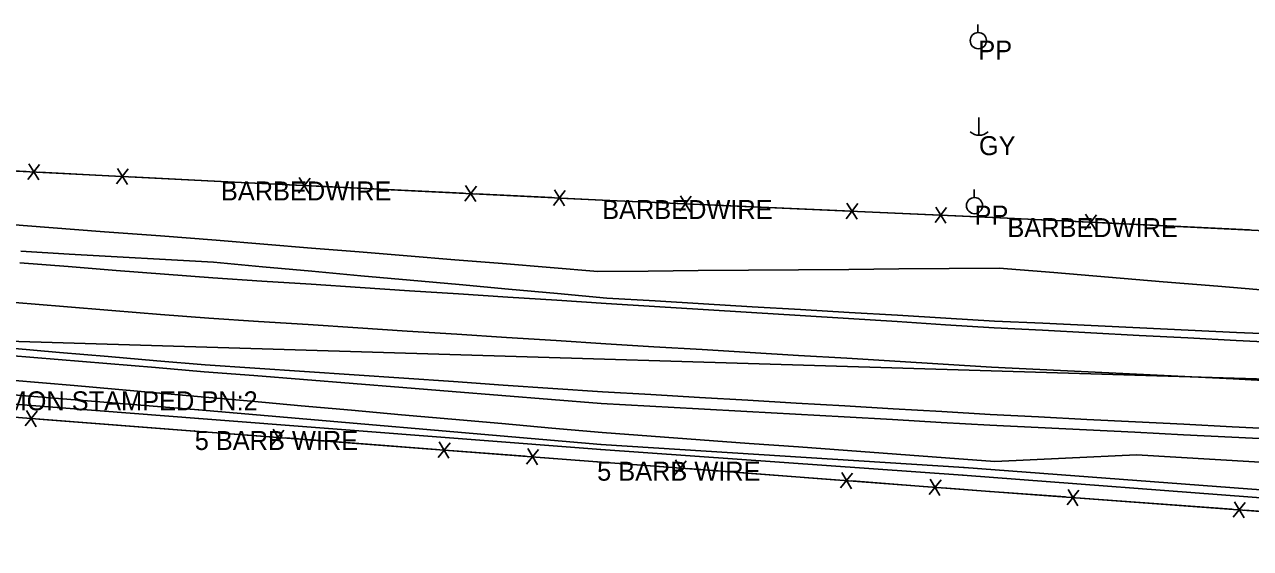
# Model space of a CAD drawing. Extents: x 675481 to 678499, y 212715 to 215285.
# Drawn here: x 675952.1 to 676275.5, y 214677.2 to 214815.3 of the extents above; entities that cross this region are included whole.
import ezdxf

# ---------------------------------------------------------------- set-up
doc = ezdxf.new("R2010")
doc.units = 0
for name, color, linetype in [('S_BASELINE', 7, 'Continuous'), ('S_DITCHLINE', 7, 'Continuous'), ('S_EDGE_PAVEMENT', 7, 'Continuous'), ('S_FENCE', 7, 'Continuous'), ('S_FENCE_ANNOT', 7, 'Continuous'), ('S_FIBER_OPTIC_CABLE', 7, 'Continuous'), ('S_MSC_PT_SYM', 7, 'Continuous'), ('S_PAVEMENT_CROWN', 7, 'Continuous'), ('S_PRIMARY_CTL_ANNOT', 7, 'Continuous'), ('S_SHOULDER', 7, 'Continuous'), ('S_UTILITY_POLE', 7, 'Continuous'), ('S_UTILITY_POLE_ANNOT', 7, 'Continuous'), ('S_UTL_PT_SYM', 7, 'Continuous')]:
    doc.layers.add(name, color=color, linetype=linetype)

msp = doc.modelspace()

# ---------------------------------------------------------------- linework, layer by layer
at = {"layer": 'S_BASELINE'}
msp.add_line((675887.93, 214733.6), (676879.32, 214703.75), dxfattribs=at)
at = {"layer": 'S_DITCHLINE'}
for points in [[(675943.76, 214762.96), (675958.47, 214761.83), (675973.19, 214760.71), (675987.9, 214759.58), (676002.61, 214758.45), (676015.2, 214757.42), (676027.79, 214756.39), (676040.37, 214755.36), (676052.96, 214754.33), (676065.55, 214753.31), (676078.13, 214752.28), (676090.72, 214751.25), (676103.31, 214750.22), (676116.54, 214750.33), (676129.78, 214750.44), (676143.02, 214750.56), (676156.25, 214750.67), (676169.49, 214750.78), (676182.72, 214750.89), (676195.96, 214751.01), (676209.2, 214751.12), (676223.61, 214749.92), (676238.03, 214748.72), (676252.45, 214747.52), (676266.87, 214746.32), (676281.29, 214745.11)], [(675948.44, 214721.58), (675965.17, 214720.1), (675981.9, 214718.63), (675998.63, 214717.15), (676011.85, 214715.97), (676025.07, 214714.8), (676038.3, 214713.62), (676051.52, 214712.44), (676064.74, 214711.27), (676077.97, 214710.09), (676091.19, 214708.91), (676104.41, 214707.74), (676117.36, 214706.79), (676130.31, 214705.84), (676143.25, 214704.88), (676156.2, 214703.93), (676169.15, 214702.98), (676182.1, 214702.03), (676195.04, 214701.08), (676207.99, 214700.13), (676226.7, 214700.98), (676245.41, 214701.83), (676266.15, 214700.62), (676286.9, 214699.42)]]:
    msp.add_lwpolyline(points, dxfattribs=at)
at = {"layer": 'S_EDGE_PAVEMENT'}
for points in [[(675950.84, 214752.51), (675963.55, 214751.51), (675976.27, 214750.51), (675988.98, 214749.52), (676001.7, 214748.52), (676014.67, 214747.68), (676027.64, 214746.83), (676040.61, 214745.99), (676053.59, 214745.15), (676066.56, 214744.31), (676079.53, 214743.46), (676092.51, 214742.62), (676105.48, 214741.78), (676118.27, 214740.98), (676131.06, 214740.18), (676143.85, 214739.38), (676156.65, 214738.58), (676169.44, 214737.78), (676182.23, 214736.98), (676195.02, 214736.18), (676207.81, 214735.38), (676220.58, 214734.71), (676233.36, 214734.04), (676246.13, 214733.37), (676258.9, 214732.7), (676271.67, 214732.03), (676284.45, 214731.36)], [(675948.5, 214729.96), (675961.32, 214728.87), (675974.13, 214727.78), (675986.94, 214726.69), (675999.75, 214725.59), (676012.85, 214724.71), (676025.94, 214723.82), (676039.04, 214722.93), (676052.13, 214722.05), (676065.22, 214721.16), (676078.32, 214720.27), (676091.41, 214719.38), (676104.5, 214718.5), (676117.29, 214717.75), (676130.08, 214717), (676142.86, 214716.26), (676155.65, 214715.51), (676168.44, 214714.76), (676181.22, 214714.02), (676194.01, 214713.27), (676206.8, 214712.52), (676219.56, 214711.87), (676232.33, 214711.22), (676245.1, 214710.56), (676257.86, 214709.91), (676270.63, 214709.26), (676283.4, 214708.6)]]:
    msp.add_lwpolyline(points, dxfattribs=at)
at = {"layer": 'S_FENCE'}
for p, q in [((675888.58, 214779.82), (676003.88, 214773.95)), ((675952.96, 214774.49), (675956.03, 214778.44)), ((675953.16, 214778.58), (675955.82, 214774.35)), ((675976.36, 214773.3), (675979.43, 214777.25)), ((675976.57, 214777.39), (675979.22, 214773.15)), ((676003.88, 214773.95), (676104.45, 214769.05)), ((676024.31, 214770.9), (676027.37, 214774.86)), ((676024.51, 214774.99), (676027.17, 214770.76)), ((676068.23, 214768.77), (676071.3, 214772.72)), ((676068.43, 214772.86), (676071.1, 214768.63)), ((676091.63, 214767.63), (676094.69, 214771.58)), ((676091.83, 214771.72), (676094.49, 214767.49)), ((676124.9, 214766.09), (676127.94, 214770.06)), ((676125.08, 214770.18), (676127.76, 214765.96)), ((676104.45, 214769.05), (676211.34, 214764.29)), ((676168.83, 214764.13), (676171.88, 214768.1)), ((676169.02, 214768.23), (676171.7, 214764.01)), ((676192.24, 214763.09), (676195.28, 214767.06)), ((676192.42, 214767.18), (676195.1, 214762.96)), ((676211.34, 214764.29), (676325.95, 214758.67)), ((676231.77, 214761.24), (676234.84, 214765.19)), ((676231.97, 214765.33), (676234.63, 214761.1)), ((675864.7, 214718.25), (675996.97, 214708.14)), ((675952.27, 214709.5), (675955.44, 214713.37)), ((675952.58, 214713.58), (675955.13, 214709.28)), ((676017.3, 214704.53), (676020.47, 214708.4)), ((676017.62, 214708.62), (676020.16, 214704.31)), ((675996.97, 214708.14), (676103.12, 214700.04)), ((676061.46, 214705.27), (676064.01, 214700.97)), ((676061.15, 214701.19), (676064.32, 214705.05)), ((676084.5, 214699.4), (676087.67, 214703.27)), ((676084.81, 214703.49), (676087.36, 214699.19)), ((676103.12, 214700.04), (676206.7, 214692.21)), ((676123.47, 214696.44), (676126.64, 214700.31)), ((676123.78, 214700.53), (676126.33, 214696.23)), ((676167.32, 214693.13), (676170.49, 214697)), ((676167.63, 214697.22), (676170.18, 214692.92)), ((676190.99, 214695.45), (676193.54, 214691.15)), ((676190.68, 214691.37), (676193.85, 214695.23)), ((676206.7, 214692.21), (676410.39, 214677.16)), ((676227.06, 214688.65), (676230.22, 214692.53)), ((676227.36, 214692.74), (676229.92, 214688.44)), ((676270.93, 214685.41), (676274.1, 214689.28)), ((676271.24, 214689.5), (676273.79, 214685.2))]:
    msp.add_line(p, q, dxfattribs=at)
for points in [[(675912.55, 214778.6), (675952.49, 214776.57)], [(675955.92, 214776.39), (675975.9, 214775.37)], [(675979.89, 214775.17), (676003.88, 214773.95)], [(676003.88, 214773.95), (676023.85, 214772.98)], [(676027.84, 214772.78), (676067.77, 214770.84)], [(676071.2, 214770.67), (676091.16, 214769.7)], [(676095.15, 214769.5), (676104.45, 214769.05)], [(676104.45, 214769.05), (676124.42, 214768.16)], [(676128.42, 214767.98), (676168.36, 214766.21)], [(676171.79, 214766.05), (676191.76, 214765.16)], [(676195.76, 214764.99), (676211.34, 214764.29)], [(676211.34, 214764.29), (676231.31, 214763.31)], [(676235.3, 214763.12), (676275.23, 214761.16)], [(675955.85, 214711.28), (675995.72, 214708.23)], [(675996.97, 214708.14), (676016.9, 214706.62)], [(676020.88, 214706.31), (676060.74, 214703.27)], [(676064.16, 214703.01), (676084.09, 214701.49)], [(676088.08, 214701.18), (676103.12, 214700.04)], [(676103.12, 214700.04), (676123.06, 214698.53)], [(676127.05, 214698.23), (676166.91, 214695.22)], [(676170.34, 214694.96), (676190.27, 214693.45)], [(676194.26, 214693.15), (676206.7, 214692.21)], [(676206.7, 214692.21), (676226.64, 214690.74)], [(676230.63, 214690.44), (676270.52, 214687.49)], [(676273.94, 214687.24), (676293.89, 214685.77)]]:
    msp.add_lwpolyline(points, dxfattribs=at)
at = {"layer": 'S_FIBER_OPTIC_CABLE'}
for p, q in [((675867.82, 214724.23), (675997.97, 214713.72)), ((675873.58, 214721.07), (675998.01, 214711.46)), ((675997.97, 214713.72), (676104.1, 214704.62)), ((675998.01, 214711.46), (676104.06, 214703.26)), ((676104.06, 214703.26), (676199.58, 214696.49)), ((676104.1, 214704.62), (676199.89, 214698.5)), ((676199.58, 214696.49), (676408.56, 214680.71)), ((676199.89, 214698.5), (676408.53, 214682.85))]:
    msp.add_line(p, q, dxfattribs=at)
at = {"layer": 'S_MSC_PT_SYM'}
for points in [[(676003.88, 214773.95), (676003.88, 214774), (676003.88, 214773.95), (676003.83, 214773.95), (676003.88, 214773.95), (676003.88, 214773.9), (676003.88, 214773.95), (676003.93, 214773.95)], [(676104.45, 214769.05), (676104.45, 214769.1), (676104.45, 214769.05), (676104.4, 214769.05), (676104.45, 214769.05), (676104.45, 214769), (676104.45, 214769.05), (676104.5, 214769.05)], [(676211.34, 214764.29), (676211.34, 214764.34), (676211.34, 214764.29), (676211.29, 214764.29), (676211.34, 214764.29), (676211.34, 214764.24), (676211.34, 214764.29), (676211.4, 214764.29)], [(675996.97, 214708.14), (675996.97, 214708.19), (675996.97, 214708.14), (675996.92, 214708.14), (675996.97, 214708.14), (675996.97, 214708.09), (675996.97, 214708.14), (675997.02, 214708.14)], [(676103.12, 214700.04), (676103.12, 214700.09), (676103.12, 214700.04), (676103.08, 214700.04), (676103.12, 214700.04), (676103.12, 214699.99), (676103.12, 214700.04), (676103.18, 214700.04)], [(676206.7, 214692.21), (676206.7, 214692.26), (676206.7, 214692.21), (676206.65, 214692.21), (676206.7, 214692.21), (676206.7, 214692.16), (676206.7, 214692.21), (676206.75, 214692.21)]]:
    msp.add_lwpolyline(points, dxfattribs=at)
at = {"layer": 'S_PAVEMENT_CROWN'}
msp.add_lwpolyline([(675949.52, 214742), (675962.31, 214740.96), (675975.11, 214739.93), (675987.91, 214738.9), (676000.7, 214737.87), (676013.79, 214737.03), (676026.87, 214736.19), (676039.95, 214735.35), (676053.04, 214734.51), (676066.12, 214733.67), (676079.2, 214732.83), (676092.29, 214731.99), (676105.37, 214731.15), (676118.09, 214730.38), (676130.81, 214729.62), (676143.52, 214728.85), (676156.24, 214728.08), (676168.96, 214727.31), (676181.68, 214726.54), (676194.4, 214725.77), (676207.11, 214725), (676219.87, 214724.37), (676232.62, 214723.74), (676245.37, 214723.12), (676258.13, 214722.49), (676270.88, 214721.86), (676283.63, 214721.23)], dxfattribs=at)
at = {"layer": 'S_SHOULDER'}
for points in [[(675951.1, 214755.53), (675963.8, 214754.81), (675976.51, 214754.09), (675989.21, 214753.38), (676001.92, 214752.66), (676014.88, 214751.47), (676027.85, 214750.29), (676040.82, 214749.11), (676053.78, 214747.92), (676066.75, 214746.74), (676079.72, 214745.55), (676092.68, 214744.37), (676105.65, 214743.19), (676118.43, 214742.43), (676131.21, 214741.68), (676144, 214740.92), (676156.78, 214740.17), (676169.56, 214739.41), (676182.35, 214738.66), (676195.13, 214737.9), (676207.91, 214737.15), (676220.69, 214736.55), (676233.47, 214735.95), (676246.25, 214735.35), (676259.02, 214734.75), (676271.8, 214734.15), (676284.58, 214733.56)], [(675948.11, 214728.06), (675960.95, 214726.99), (675973.79, 214725.92), (675986.63, 214724.85), (675999.47, 214723.79), (676012.56, 214722.74), (676025.65, 214721.7), (676038.74, 214720.66), (676051.82, 214719.61), (676064.91, 214718.57), (676078, 214717.53), (676091.09, 214716.48), (676104.18, 214715.44), (676117, 214714.72), (676129.81, 214714.01), (676142.62, 214713.29), (676155.43, 214712.57), (676168.24, 214711.86), (676181.06, 214711.14), (676193.87, 214710.42), (676206.68, 214709.71), (676219.45, 214709.07), (676232.22, 214708.44), (676244.99, 214707.8), (676257.75, 214707.17), (676270.52, 214706.53), (676283.29, 214705.9)]]:
    msp.add_lwpolyline(points, dxfattribs=at)
at = {"layer": 'S_UTILITY_POLE'}
for p, q in [((676203.55, 214813.24), (676203.55, 214815.35)), ((676203.81, 214790.85), (676203.81, 214786.12)), ((676202.55, 214769.73), (676202.55, 214771.84))]:
    msp.add_line(p, q, dxfattribs=at)
for centre in [(676203.67, 214811.1), (676202.67, 214767.59)]:
    msp.add_circle(centre, 2.13, dxfattribs=at)
msp.add_arc((676203.87, 214789.55), 3.41, 226.3972, 313.6028, dxfattribs=at)
at = {"layer": 'S_UTL_PT_SYM'}
for points in [[(675997.97, 214713.72), (675997.97, 214713.77), (675997.97, 214713.72), (675997.92, 214713.72), (675997.97, 214713.72), (675997.97, 214713.67), (675997.97, 214713.72), (675998.03, 214713.72)], [(675998.01, 214711.46), (675998.01, 214711.51), (675998.01, 214711.46), (675997.96, 214711.46), (675998.01, 214711.46), (675998.01, 214711.41), (675998.01, 214711.46), (675998.06, 214711.46)], [(676104.06, 214703.26), (676104.06, 214703.3), (676104.06, 214703.26), (676104.01, 214703.26), (676104.06, 214703.26), (676104.06, 214703.21), (676104.06, 214703.26), (676104.11, 214703.26)], [(676104.1, 214704.62), (676104.1, 214704.67), (676104.1, 214704.62), (676104.05, 214704.62), (676104.1, 214704.62), (676104.1, 214704.57), (676104.1, 214704.62), (676104.16, 214704.62)], [(676199.58, 214696.49), (676199.58, 214696.54), (676199.58, 214696.49), (676199.53, 214696.49), (676199.58, 214696.49), (676199.58, 214696.44), (676199.58, 214696.49), (676199.63, 214696.49)], [(676199.89, 214698.5), (676199.89, 214698.55), (676199.89, 214698.5), (676199.84, 214698.5), (676199.89, 214698.5), (676199.89, 214698.45), (676199.89, 214698.5), (676199.94, 214698.5)]]:
    msp.add_lwpolyline(points, dxfattribs=at)

# ---------------------------------------------------------------- texts
at = {"layer": 'S_FENCE_ANNOT'}
for s, p in [('BARBEDWIRE', (676003.88, 214768.95)), ('BARBEDWIRE', (676104.45, 214764.05)), ('BARBEDWIRE', (676211.34, 214759.29)), ('5 BARB WIRE', (675996.97, 214703.14)), ('5 BARB WIRE', (676103.12, 214695.04))]:
    msp.add_text(s, height=5, dxfattribs=at).set_placement(p)
at = {"layer": 'S_PRIMARY_CTL_ANNOT'}
msp.add_text('PD:STD ARDOT MON STAMPED PN:2', height=5, dxfattribs=at).set_placement((675895.43, 214713.6))
at = {"layer": 'S_UTILITY_POLE_ANNOT'}
for s, p in [('PP', (676203.67, 214806.1)), ('GY', (676203.83, 214780.9)), ('PP', (676202.67, 214762.59))]:
    msp.add_text(s, height=5, dxfattribs=at).set_placement(p)

doc.saveas('drawing.dxf')
